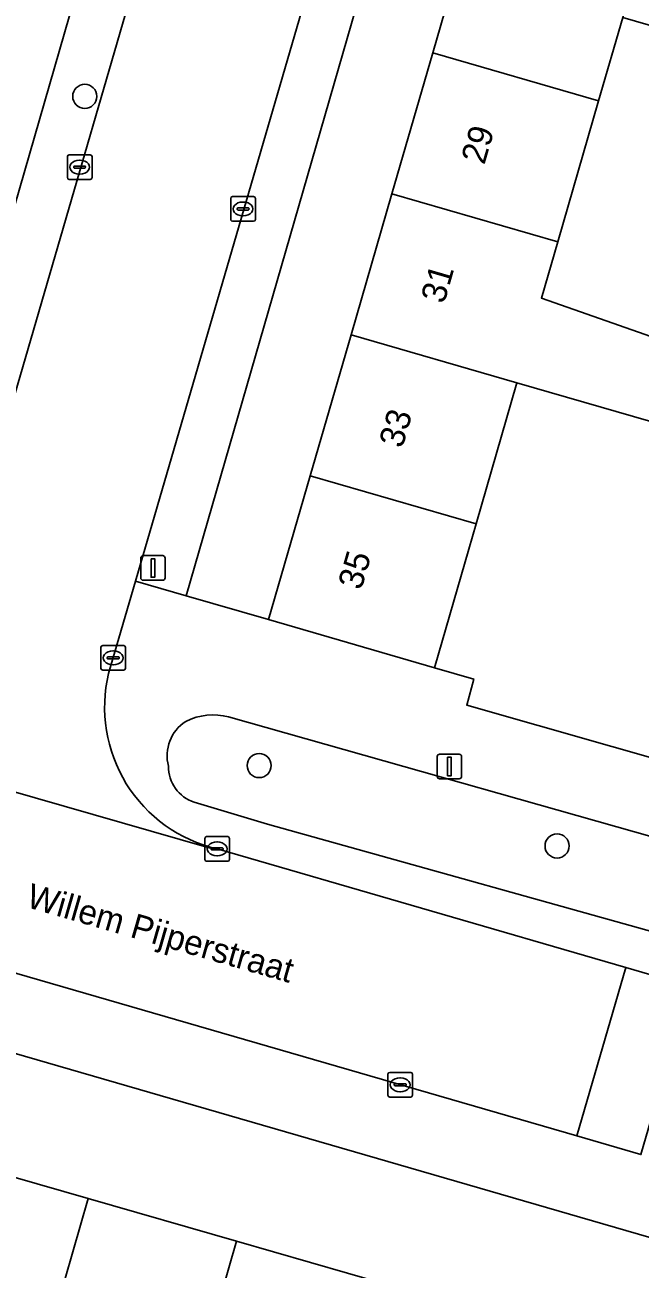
# Model space of a CAD drawing. Extents: x 159817 to 160765, y 380688 to 381638.
# Drawn here: x 160351 to 160376, y 381162.8 to 381213.2 of the extents above; entities that cross this region are included whole.
import ezdxf

# ---------------------------------------------------------------- set-up
doc = ezdxf.new("R2010")
doc.units = 0
for name, color, linetype in [('IMGEO_Boom', 7, 'Continuous'), ('IMGEO_Erf', 7, 'Continuous'), ('IMGEO_Groenvoorziening', 7, 'Continuous'), ('IMGEO_Haag', 7, 'Continuous'), ('IMGEO_Kolk', 7, 'Continuous'), ('IMGEO_Lichtmast', 7, 'Continuous'), ('IMGEO_Muur', 7, 'Continuous'), ('IMGEO_Openbare_ruimte_label', 7, 'Continuous'), ('IMGEO_Pand', 7, 'Continuous'), ('IMGEO_Pand_nummerreeks', 7, 'Continuous'), ('IMGEO_Rijbaan_lokaal_open', 7, 'Continuous'), ('IMGEO_Voetpad_open', 7, 'Continuous')]:
    doc.layers.add(name, color=color, linetype=linetype)

msp = doc.modelspace()

# ---------------------------------------------------------------- linework, layer by layer
at = {"layer": 'IMGEO_Boom'}
for centre in [(160353.452, 381210.289), (160360.523, 381183.167), (160372.604, 381179.908)]:
    msp.add_circle(centre, 0.489, dxfattribs=at)
at = {"layer": 'IMGEO_Erf'}
for points in [[(160369.217, 381217.763), (160370.872, 381223.476), (160372.558, 381229.306), (160369.194, 381230.279), (160357.559, 381190.045), (160360.908, 381189.081), (160362.598, 381194.909), (160364.253, 381200.624), (160365.908, 381206.337), (160367.563, 381212.051)], [(160353.653, 381216.434), (160349.848, 381217.533), (160348.143, 381211.647), (160346.472, 381205.877), (160344.801, 381200.107), (160343.097, 381194.222), (160346.926, 381193.142)], [(160384.423, 381194.783), (160384.273, 381194.829), (160383.807, 381193.114), (160377.896, 381194.721), (160378.419, 381196.524), (160370.976, 381198.678), (160369.32, 381192.963), (160369.023, 381191.937), (160367.632, 381187.134), (160369.227, 381186.672), (160368.941, 381185.618), (160377.72, 381183.111), (160378.572, 381186.094), (160381.38, 381185.291), (160383.908, 381192.892)], [(160387.463, 381147.685), (160381.456, 381149.414), (160375.447, 381151.142), (160369.441, 381152.87), (160363.433, 381154.598), (160357.426, 381156.326), (160351.418, 381158.055), (160345.296, 381159.816), (160347.471, 381167.376), (160353.593, 381165.615), (160359.601, 381163.887), (160365.608, 381162.159), (160371.616, 381160.43), (160377.622, 381158.703), (160383.631, 381156.974), (160389.638, 381155.246), (160395.644, 381153.518), (160401.771, 381151.756), (160400.922, 381148.803), (160406.891, 381147.056), (160404.695, 381139.55), (160398.613, 381141.351), (160399.462, 381144.234), (160393.469, 381145.958)]]:
    msp.add_lwpolyline(points, close=True, dxfattribs=at)
for points in [[(160378.437, 381214.799), (160377.842, 381212.745), (160375.266, 381213.49), (160374.285, 381210.104), (160372.63, 381204.391), (160371.971, 381202.114), (160379.292, 381199.54), (160378.831, 381197.95), (160384.689, 381196.358), (160384.273, 381194.829), (160384.423, 381194.783), (160384.84, 381196.317), (160387.028, 381204.371), (160386.996, 381204.38), (160381.152, 381205.967), (160381.693, 381207.96), (160382.083, 381209.393), (160387.926, 381207.806), (160388.332, 381209.293), (160384.57, 381210.315), (160385.212, 381212.678), (160388.974, 381211.656), (160390.114, 381215.858)], [(160407.146, 381155.127), (160345.496, 381172.978)]]:
    msp.add_lwpolyline(points, dxfattribs=at)
at = {"layer": 'IMGEO_Groenvoorziening'}
for points in [[(160379.706, 381179.362), (160359.285, 381185.142)], [(160357.888, 381181.68), (160360.864, 381180.788), (160378.663, 381175.827), (160379.706, 381179.362)]]:
    msp.add_lwpolyline(points, dxfattribs=at)
for centre, radius, start, end in [((160358.453, 381183.562), 1.662, 122.9901, 194.6643), ((160358.66, 381182.772), 2.451, 75.2304, 116.9936), ((160358.387, 381183.139), 1.542, 179.9221, 251.1236)]:
    msp.add_arc(centre, radius, start, end, dxfattribs=at)
at = {"layer": 'IMGEO_Haag'}
msp.add_lwpolyline([(160357.888, 381181.68), (160360.864, 381180.788), (160378.663, 381175.827), (160379.706, 381179.362), (160359.285, 381185.142)], dxfattribs=at)
for centre, radius, start, end in [((160358.453, 381183.562), 1.662, 122.9901, 194.6643), ((160358.66, 381182.772), 2.451, 75.2304, 116.9936), ((160358.387, 381183.139), 1.542, 179.9221, 251.1236)]:
    msp.add_arc(centre, radius, start, end, dxfattribs=at)
at = {"layer": 'IMGEO_Kolk'}
for p, q in [((160352.746, 381206.994), (160352.746, 381207.846)), ((160352.821, 381207.92), (160353.673, 381207.92)), ((160353.005, 381207.414), (160353.005, 381207.426)), ((160353.048, 381207.463), (160353.446, 381207.463)), ((160353.234, 381207.7), (160353.259, 381207.7)), ((160353.489, 381207.426), (160353.489, 381207.414)), ((160353.747, 381207.846), (160353.747, 381206.994)), ((160353.673, 381206.92), (160352.821, 381206.92)), ((160353.443, 381207.377), (160353.045, 381207.377)), ((160353.257, 381207.14), (160353.232, 381207.14)), ((160359.37, 381205.3), (160359.37, 381206.152)), ((160359.445, 381206.226), (160360.297, 381206.226)), ((160359.858, 381206.006), (160359.883, 381206.006)), ((160360.371, 381206.152), (160360.371, 381205.3)), ((160359.629, 381205.72), (160359.629, 381205.732)), ((160360.067, 381205.683), (160359.669, 381205.683)), ((160359.672, 381205.769), (160360.07, 381205.769)), ((160359.881, 381205.446), (160359.856, 381205.446)), ((160360.113, 381205.732), (160360.113, 381205.72)), ((160360.297, 381205.226), (160359.445, 381205.226)), ((160354.103, 381187.107), (160354.103, 381187.959)), ((160354.178, 381188.033), (160355.03, 381188.033)), ((160354.591, 381187.813), (160354.616, 381187.813)), ((160355.104, 381187.959), (160355.104, 381187.107)), ((160354.362, 381187.527), (160354.362, 381187.539)), ((160354.8, 381187.49), (160354.402, 381187.49)), ((160354.405, 381187.576), (160354.803, 381187.576)), ((160354.614, 381187.253), (160354.589, 381187.253)), ((160354.846, 381187.539), (160354.846, 381187.527)), ((160355.03, 381187.033), (160354.178, 381187.033)), ((160358.319, 381179.364), (160358.319, 381180.216)), ((160358.394, 381180.29), (160359.246, 381180.29)), ((160359.32, 381180.216), (160359.32, 381179.364)), ((160358.578, 381179.784), (160358.578, 381179.796)), ((160359.016, 381179.747), (160358.618, 381179.747)), ((160358.621, 381179.833), (160359.019, 381179.833)), ((160358.807, 381180.07), (160358.832, 381180.07)), ((160359.062, 381179.796), (160359.062, 381179.784)), ((160359.246, 381179.29), (160358.394, 381179.29)), ((160358.83, 381179.51), (160358.805, 381179.51)), ((160365.741, 381169.804), (160365.741, 381170.656)), ((160365.816, 381170.73), (160366.668, 381170.73)), ((160366.742, 381170.656), (160366.742, 381169.804)), ((160366, 381170.224), (160366, 381170.236)), ((160366.438, 381170.187), (160366.04, 381170.187)), ((160366.043, 381170.273), (160366.441, 381170.273)), ((160366.229, 381170.51), (160366.254, 381170.51)), ((160366.484, 381170.236), (160366.484, 381170.224)), ((160366.668, 381169.73), (160365.816, 381169.73)), ((160366.252, 381169.95), (160366.227, 381169.95))]:
    msp.add_line(p, q, dxfattribs=at)
for points in [[(160352.746, 381206.994), (160352.746, 381207.846)], [(160352.821, 381207.92), (160353.673, 381207.92)], [(160353.747, 381207.846), (160353.747, 381206.994)], [(160353.673, 381206.92), (160352.821, 381206.92)], [(160359.37, 381205.3), (160359.37, 381206.152)], [(160359.445, 381206.226), (160360.297, 381206.226)], [(160360.371, 381206.152), (160360.371, 381205.3)], [(160360.297, 381205.226), (160359.445, 381205.226)], [(160354.103, 381187.107), (160354.103, 381187.959)], [(160354.178, 381188.033), (160355.03, 381188.033)], [(160355.104, 381187.959), (160355.104, 381187.107)], [(160355.03, 381187.033), (160354.178, 381187.033)], [(160358.319, 381179.364), (160358.319, 381180.216)], [(160358.394, 381180.29), (160359.246, 381180.29)], [(160359.32, 381180.216), (160359.32, 381179.364)], [(160359.246, 381179.29), (160358.394, 381179.29)], [(160365.741, 381169.804), (160365.741, 381170.656)], [(160365.816, 381170.73), (160366.668, 381170.73)], [(160366.742, 381170.656), (160366.742, 381169.804)], [(160366.668, 381169.73), (160365.816, 381169.73)]]:
    msp.add_lwpolyline(points, dxfattribs=at)
for centre, radius, start, end in [((160352.823, 381207.844), 0.0765, 91.552, 178.448), ((160352.823, 381207.844), 0.0765, 91.552, 178.448), ((160353.045, 381207.423), 0.0403, 85.8775, 175.7526), ((160353.45, 381207.425), 0.0386, 1.7309, 96.639), ((160353.671, 381207.844), 0.0765, 1.552, 88.448), ((160353.671, 381207.844), 0.0765, 1.552, 88.448), ((160352.823, 381206.996), 0.0765, 181.552, 268.448), ((160352.823, 381206.996), 0.0765, 181.552, 268.448), ((160353.042, 381207.413), 0.0366, 178.938, 274.7102), ((160353.446, 381207.42), 0.043, 264.8664, 352.4533), ((160353.671, 381206.996), 0.0765, 271.552, 358.448), ((160353.671, 381206.996), 0.0765, 271.552, 358.448), ((160359.447, 381206.15), 0.0765, 91.552, 178.448), ((160359.447, 381206.15), 0.0765, 91.552, 178.448), ((160360.295, 381206.15), 0.0765, 1.552, 88.448), ((160360.295, 381206.15), 0.0765, 1.552, 88.448), ((160359.669, 381205.729), 0.0403, 85.8775, 175.7526), ((160359.666, 381205.719), 0.0366, 178.938, 274.7102), ((160360.07, 381205.726), 0.043, 264.8664, 352.4533), ((160360.074, 381205.731), 0.0386, 1.7309, 96.639), ((160359.447, 381205.302), 0.0765, 181.552, 268.448), ((160359.447, 381205.302), 0.0765, 181.552, 268.448), ((160360.295, 381205.302), 0.0765, 271.552, 358.448), ((160360.295, 381205.302), 0.0765, 271.552, 358.448), ((160354.18, 381187.957), 0.0765, 91.552, 178.448), ((160354.18, 381187.957), 0.0765, 91.552, 178.448), ((160355.028, 381187.957), 0.0765, 1.552, 88.448), ((160355.028, 381187.957), 0.0765, 1.552, 88.448), ((160354.402, 381187.536), 0.0403, 85.8775, 175.7526), ((160354.399, 381187.526), 0.0366, 178.938, 274.7102), ((160354.803, 381187.533), 0.043, 264.8664, 352.4533), ((160354.807, 381187.538), 0.0386, 1.7309, 96.639), ((160354.18, 381187.109), 0.0765, 181.552, 268.448), ((160354.18, 381187.109), 0.0765, 181.552, 268.448), ((160355.028, 381187.109), 0.0765, 271.552, 358.448), ((160355.028, 381187.109), 0.0765, 271.552, 358.448), ((160358.396, 381180.214), 0.0765, 91.552, 178.448), ((160358.396, 381180.214), 0.0765, 91.552, 178.448), ((160359.244, 381180.214), 0.0765, 1.552, 88.448), ((160359.244, 381180.214), 0.0765, 1.552, 88.448), ((160358.618, 381179.793), 0.0403, 85.8775, 175.7526), ((160358.615, 381179.783), 0.0366, 178.938, 274.7102), ((160359.019, 381179.79), 0.043, 264.8664, 352.4533), ((160359.023, 381179.795), 0.0386, 1.7309, 96.639), ((160358.396, 381179.366), 0.0765, 181.552, 268.448), ((160358.396, 381179.366), 0.0765, 181.552, 268.448), ((160359.244, 381179.366), 0.0765, 271.552, 358.448), ((160359.244, 381179.366), 0.0765, 271.552, 358.448), ((160365.818, 381170.654), 0.0765, 91.552, 178.448), ((160365.818, 381170.654), 0.0765, 91.552, 178.448), ((160366.666, 381170.654), 0.0765, 1.552, 88.448), ((160366.666, 381170.654), 0.0765, 1.552, 88.448), ((160366.04, 381170.233), 0.0403, 85.8775, 175.7526), ((160366.037, 381170.223), 0.0366, 178.938, 274.7102), ((160366.441, 381170.23), 0.043, 264.8664, 352.4533), ((160366.445, 381170.235), 0.0386, 1.7309, 96.639), ((160365.818, 381169.806), 0.0765, 181.552, 268.448), ((160365.818, 381169.806), 0.0765, 181.552, 268.448), ((160366.666, 381169.806), 0.0765, 271.552, 358.448), ((160366.666, 381169.806), 0.0765, 271.552, 358.448)]:
    msp.add_arc(centre, radius, start, end, dxfattribs=at)
for centre, major_axis, ratio, start_param, end_param in [((160353.233, 381207.42), (-0.387, 0.002), 0.722429, 4.712389, 7.853982), ((160353.258, 381207.42), (-0.39, 0.002), 0.717154, 1.570796, 4.712389), ((160359.857, 381205.726), (-0.387, 0.002), 0.722429, 4.712389, 7.853982), ((160359.882, 381205.726), (-0.39, 0.002), 0.717154, 1.570796, 4.712389), ((160354.59, 381187.533), (-0.387, 0.002), 0.722429, 4.712389, 7.853982), ((160354.615, 381187.533), (-0.39, 0.002), 0.717154, 1.570796, 4.712389), ((160358.806, 381179.79), (-0.387, 0.002), 0.722429, 4.712389, 7.853982), ((160358.831, 381179.79), (-0.39, 0.002), 0.717154, 1.570796, 4.712389), ((160366.228, 381170.23), (-0.387, 0.002), 0.722429, 4.712389, 7.853982), ((160366.253, 381170.23), (-0.39, 0.002), 0.717154, 1.570796, 4.712389)]:
    msp.add_ellipse(centre, major_axis=major_axis, ratio=ratio, start_param=start_param, end_param=end_param, dxfattribs=at)
at = {"layer": 'IMGEO_Lichtmast'}
for p, q in [((160355.721, 381190.776), (160355.721, 381191.576)), ((160355.721, 381191.576), (160355.721, 381190.776)), ((160355.821, 381191.676), (160356.611, 381191.676)), ((160356.611, 381191.676), (160355.821, 381191.676)), ((160356.711, 381191.576), (160356.711, 381190.776)), ((160356.711, 381190.776), (160356.711, 381191.576)), ((160356.611, 381190.676), (160355.821, 381190.676)), ((160355.821, 381190.676), (160356.611, 381190.676)), ((160367.742, 381182.73), (160367.742, 381183.53)), ((160367.742, 381183.53), (160367.742, 381182.73)), ((160367.842, 381183.63), (160368.632, 381183.63)), ((160368.632, 381183.63), (160367.842, 381183.63)), ((160368.732, 381183.53), (160368.732, 381182.73)), ((160368.732, 381182.73), (160368.732, 381183.53)), ((160368.632, 381182.63), (160367.842, 381182.63)), ((160367.842, 381182.63), (160368.632, 381182.63))]:
    msp.add_line(p, q, dxfattribs=at)
for points in [[(160356.141, 381191.551), (160356.291, 381191.551), (160356.291, 381190.801), (160356.141, 381190.801), (160356.141, 381191.551)], [(160368.162, 381183.505), (160368.312, 381183.505), (160368.312, 381182.755), (160368.162, 381182.755), (160368.162, 381183.505)]]:
    msp.add_lwpolyline(points, dxfattribs=at)
for centre, start, end in [((160355.821, 381191.576), 90, 180), ((160355.821, 381191.576), 90, 180), ((160356.611, 381191.576), 0, 90), ((160356.611, 381191.576), 360, 90), ((160355.821, 381190.776), 180, 270), ((160355.821, 381190.776), 180, 270), ((160356.611, 381190.776), 270, 0), ((160356.611, 381190.776), 270, 0), ((160367.842, 381183.53), 90, 180), ((160367.842, 381183.53), 90, 180), ((160368.632, 381183.53), 0, 90), ((160368.632, 381183.53), 360, 90), ((160367.842, 381182.73), 180, 270), ((160367.842, 381182.73), 180, 270), ((160368.632, 381182.73), 270, 0), ((160368.632, 381182.73), 270, 0)]:
    msp.add_arc(centre, 0.1, start, end, dxfattribs=at)
at = {"layer": 'IMGEO_Muur'}
msp.add_lwpolyline([(160367.632, 381187.134), (160369.227, 381186.672)], dxfattribs=at)
at = {"layer": 'IMGEO_Pand'}
for points in [[(160375.861, 381215.544), (160375.94, 381215.817), (160369.217, 381217.763), (160367.563, 381212.051), (160374.285, 381210.104), (160375.266, 381213.49)], [(160365.908, 381206.337), (160372.63, 381204.391), (160374.285, 381210.104), (160367.563, 381212.051)], [(160365.908, 381206.337), (160364.253, 381200.624), (160370.976, 381198.678), (160378.419, 381196.524), (160378.831, 381197.95), (160379.292, 381199.54), (160371.971, 381202.114), (160372.63, 381204.391)], [(160369.32, 381192.963), (160370.976, 381198.678), (160364.253, 381200.624), (160362.598, 381194.909)], [(160369.32, 381192.963), (160362.598, 381194.909), (160360.908, 381189.081), (160367.632, 381187.134), (160369.023, 381191.937)], [(160353.593, 381165.615), (160347.471, 381167.376), (160345.296, 381159.816), (160351.418, 381158.055)], [(160359.601, 381163.887), (160353.593, 381165.615), (160351.418, 381158.055), (160357.426, 381156.326)], [(160359.601, 381163.887), (160357.426, 381156.326), (160363.433, 381154.598), (160365.608, 381162.159)]]:
    msp.add_lwpolyline(points, close=True, dxfattribs=at)
at = {"layer": 'IMGEO_Rijbaan_lokaal_open'}
for points in [[(160368.215, 381234.221), (160370.337, 381241.568), (160363.734, 381243.436), (160361.67, 381236.217), (160348.958, 381192.55), (160348.065, 381189.456)], [(160354.42, 381186.901), (160355.503, 381190.644), (160368.215, 381234.221)], [(160340.664, 381184.965), (160340.752, 381184.93), (160358.49, 381179.827), (160358.816, 381179.79)]]:
    msp.add_lwpolyline(points, dxfattribs=at)
for points in [[(160340.664, 381184.965), (160314.255, 381192.573), (160312.301, 381185.861), (160329.797, 381180.826), (160329.938, 381180.803), (160346.8, 381175.9), (160346.957, 381175.818), (160373.409, 381168.155), (160375.389, 381174.985), (160358.816, 381179.79), (160358.49, 381179.827), (160340.752, 381184.93)], [(160377.982, 381174.233), (160375.389, 381174.985), (160373.409, 381168.155), (160376.002, 381167.404)]]:
    msp.add_lwpolyline(points, close=True, dxfattribs=at)
msp.add_arc((160360.145, 381185.526), 5.888, 166.4977, 256.9508, dxfattribs=at)
at = {"layer": 'IMGEO_Voetpad_open'}
for points in [[(160378.693, 381297.546), (160377.296, 381298.306), (160367.267, 381263.577), (160366.293, 381260.204), (160363.346, 381250), (160354.607, 381219.739), (160353.653, 381216.434), (160346.926, 381193.142), (160348.958, 381192.55), (160361.67, 381236.217), (160363.734, 381243.436), (160364.487, 381246.013)], [(160385.528, 381294.362), (160374.029, 381254.391), (160372.118, 381247.759), (160371.067, 381244.133), (160370.337, 381241.568), (160368.215, 381234.221), (160355.503, 381190.644), (160357.559, 381190.045), (160369.194, 381230.279), (160369.89, 381232.684), (160374.897, 381250)], [(160369.227, 381186.672), (160367.632, 381187.134), (160360.908, 381189.081), (160357.559, 381190.045), (160355.503, 381190.644), (160354.42, 381186.901)], [(160409.071, 381171.801), (160410.006, 381174.977), (160407.24, 381175.79), (160403.48, 381176.846), (160395.637, 381179.159), (160394.134, 381179.602), (160393.79, 381178.521), (160385.351, 381180.931), (160382.265, 381181.813), (160380.528, 381182.308), (160377.72, 381183.111), (160368.941, 381185.618), (160369.227, 381186.672)], [(160359.285, 381185.142), (160379.706, 381179.362)], [(160379.706, 381179.362), (160378.663, 381175.827), (160360.864, 381180.788), (160357.888, 381181.68)], [(160358.816, 381179.79), (160375.389, 381174.985), (160377.982, 381174.233), (160399.632, 381167.956), (160402.597, 381167.098)], [(160376.002, 381167.404), (160373.409, 381168.155), (160346.957, 381175.818)], [(160342.299, 381175.418), (160345.496, 381172.978), (160407.146, 381155.127), (160412.248, 381153.013)]]:
    msp.add_lwpolyline(points, dxfattribs=at)
for centre, radius, start, end in [((160360.145, 381185.526), 5.888, 166.4977, 256.9508), ((160358.453, 381183.562), 1.662, 122.9901, 194.6643), ((160358.66, 381182.772), 2.451, 75.2304, 116.9936), ((160358.387, 381183.139), 1.542, 179.9221, 251.1236)]:
    msp.add_arc(centre, radius, start, end, dxfattribs=at)

# ---------------------------------------------------------------- texts
at = {"layer": 'IMGEO_Openbare_ruimte_label'}
msp.add_text('Willem Pijperstraat', height=1, rotation=343.9208, dxfattribs=at).set_placement((160351.033, 381177.444))
at = {"layer": 'IMGEO_Pand_nummerreeks'}
for s, p in [('29', (160369.654, 381207.488)), ('31', (160368.021, 381201.85)), ('33', (160366.325, 381195.995)), ('35', (160364.661, 381190.248))]:
    msp.add_text(s, height=1, rotation=73.8479, dxfattribs=at).set_placement(p)

doc.saveas('drawing.dxf')
